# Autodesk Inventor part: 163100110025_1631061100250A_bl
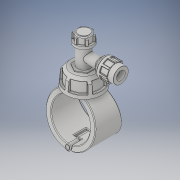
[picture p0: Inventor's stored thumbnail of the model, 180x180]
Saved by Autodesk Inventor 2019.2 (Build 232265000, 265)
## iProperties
Created: 2022-02
Part Number: 163100110025_1631061100250A_bl
Material: Generic
Description: Plassadle Tapper 110x25
Document SubType Name: Modeling
Designer: comp2
Density: 1 g/cm^3
Appearance: Default
Author: comp2
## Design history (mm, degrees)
derived "16310.ipt"
feature "Solid1::16310.ipt" dims "ScaleForDerivedMember" = 10
feature "Solid2::16310.ipt" dims "ScaleForDerivedMember" = 10
feature "Solid3::16310.ipt" dims "ScaleForDerivedMember" = 10
feature "Solid4::16310.ipt" dims "ScaleForDerivedMember" = 10
tag "TaggingFeature1"
body "Solid1"
body "Solid2"
body "Solid3"
body "Solid4"
other parameters: "d1" = 25 [user parameter], "B" = 141 [user parameter], "L" = 97 [user parameter], "E_" = 54 [user parameter], "E1" = 102 [user parameter], "H1" = 273 [user parameter], "H2" = 144 [user parameter], "H3" = 106 [user parameter], "H_costum" = 49 [user parameter], "d2" = 141 [user parameter], "d3" = 55 [user parameter], "d5" = 273 [user parameter], "d7" = 133.95 [user parameter], "d8" = 85 deg [user parameter], "d9" = 45 deg [user parameter], "d10" = 102 [user parameter], "d11" = 49 [user parameter], "d12" = 34.3 [user parameter], "d13" = 35.7 [user parameter], "d14" = 55.08 [user parameter], "d15" = 2.45 [user parameter], "d16" = 2 [user parameter], "d17" = 2 [user parameter], "d18" = 29.4 [user parameter], "d19" = 7.35 [user parameter], "d20" = 1 [user parameter], "d21" = 30.6 [user parameter], "d22" = 1 [user parameter], "d23" = 14.7 [user parameter], "d24" = 106 [user parameter], "d27" = 144 [user parameter], "d29" = 54 [user parameter], "d31" = 43.2 [user parameter], "d32" = 42.4 [user parameter], "d33" = 14.84 [user parameter], "d34" = 93 deg [user parameter], "d35" = 2 [user parameter], "d36" = 4 [user parameter], "d39" = 45 deg [user parameter], "d40" = 4 [user parameter], "d41" = 5 [user parameter], "d42" = 3.1 [user parameter], "d46" = 51 [user parameter], "d47" = 27 [user parameter], "d48" = 49 [user parameter], "d49" = 2.82 [user parameter], "d50" = 97 [user parameter], "d51" = 0 [user parameter], "d52" = 21.7 [user parameter], "d53" = 77.55 [user parameter], "d54" = 33.95 [user parameter], "d55" = 0 [user parameter], "d56" = 19.4 [user parameter], "d57" = 19.4 [user parameter], "d59" = 0 [user parameter], "d60" = 97 [user parameter], "d61" = 0 [user parameter], "d62" = 33.95 [user parameter], "d63" = 0 [user parameter], "d65" = 0 [user parameter], "d67" = 0 [user parameter], "d69" = 0 [user parameter], "d70" = 1 [user parameter], "d71" = 93.12 [user parameter], "d72" = 0 [user parameter], "d73" = 2 [user parameter], "d77" = 25 [user parameter], "d78" = 86.7 [user parameter], "d79" = 5.1 [user parameter], "d80" = 60 deg [user parameter], "d81" = 5.1 [user parameter], "d84" = 0 [user parameter], "d85" = 1 [user parameter], "d87" = 360 deg [user parameter], "d90" = 0 [user parameter], "d91" = 1 [user parameter], "d93" = 60 deg [user parameter], "d94" = 3.06 [user parameter], "d95" = 3.06 [user parameter], "d97" = 0 [user parameter], "d98" = 0.5 [user parameter], "d100" = 360 deg [user parameter], "d102" = 2 [user parameter], "d105" = 0 [user parameter], "d106" = 45 deg [user parameter], "d107" = 2.7 [user parameter], "d108" = 2.7 [user parameter], "d109" = 2.95332 [user parameter], "d110" = -8 [user parameter], "d112" = 0 [user parameter], "d113" = 0.5 [user parameter], "d115" = 360 deg [user parameter], "d117" = 0.5 [user parameter]
